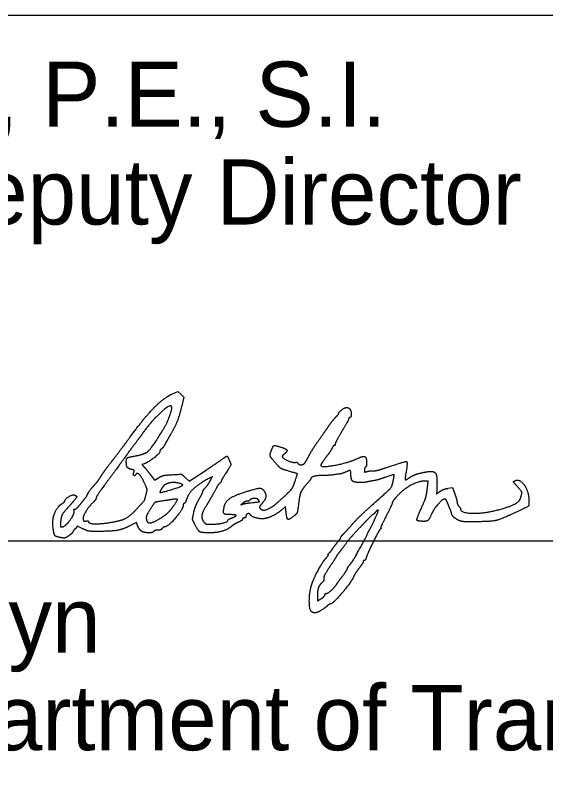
# Model space of a CAD drawing. Extents: x 36.7 to 70.7, y 0 to 22.
# Drawn here: x 62.37 to 63.51, y 7.302 to 8.923 of the extents above; entities that cross this region are included whole.
import ezdxf

# ---------------------------------------------------------------- set-up
doc = ezdxf.new("R2010")
doc.units = 0
for name, color, linetype in [('Default', 7, 'Continuous'), ('SH_Data', 7, 'Continuous'), ('SH_Text', 7, 'Continuous')]:
    doc.layers.add(name, color=color, linetype=linetype)

msp = doc.modelspace()

# ---------------------------------------------------------------- linework, layer by layer
at = {"layer": 'Default'}
for points in [[(62.7066, 8.1089), (62.7192, 8.1148), (62.7255, 8.1084), (62.7319, 8.102), (62.7275, 8.0834)], [(62.6466, 7.959), (62.6416, 7.9574), (62.6468, 7.9522)], [(62.6605, 7.9356), (62.669, 7.924), (62.6778, 7.9293)], [(62.7356, 7.9293), (62.7437, 7.9216), (62.78, 7.9457)], [(62.7895, 7.924), (62.7939, 7.9319), (62.7884, 7.929)], [(63.2553, 7.9081), (63.2568, 7.9219), (63.249, 7.9219)], [(63.2992, 7.9065), (63.3088, 7.908), (63.3139, 7.8944)], [(62.9512, 7.8603), (62.9506, 7.8671), (62.9447, 7.862)], [(62.6336, 7.8247), (62.6303, 7.8327), (62.6164, 7.8259)], [(62.515, 7.8197), (62.5035, 7.8254), (62.4984, 7.8196)], [(63.019, 7.6742), (63.019, 7.6648), (63.0265, 7.6691)]]:
    msp.add_lwpolyline(points, dxfattribs=at)
for points in [[(62.617, 8.017), (62.6467, 8.0576), (62.6885, 8.1005), (62.7066, 8.1089)], [(62.7051, 8.0831), (62.7015, 8.0868), (62.6629, 8.0511), (62.6475, 8.0298)], [(62.6868, 8.0311), (62.6962, 8.046), (62.7082, 8.08), (62.7051, 8.0831)], [(62.7275, 8.0834), (62.7225, 8.0622), (62.7133, 8.0386), (62.7039, 8.0227)], [(63.0646, 8.067), (63.0646, 8.0698), (63.0778, 8.0801), (63.0815, 8.0802)], [(63.0815, 8.0802), (63.0836, 8.0802), (63.0865, 8.079), (63.0881, 8.0774)], [(63.0881, 8.0774), (63.0916, 8.0739), (63.092, 8.0587), (63.0886, 8.0587)], [(63.058, 8.0589), (63.0616, 8.0625), (63.0646, 8.0662), (63.0646, 8.067)], [(63.0442, 8.0417), (63.0482, 8.0475), (63.0544, 8.0553), (63.058, 8.0589)], [(63.0862, 8.0562), (63.0862, 8.0548), (63.0797, 8.0427), (63.0718, 8.0293)], [(63.0886, 8.0587), (63.0873, 8.0587), (63.0862, 8.0575), (63.0862, 8.0562)], [(62.6475, 8.0298), (62.6439, 8.0248), (62.6345, 8.0121), (62.6266, 8.0016)], [(62.6763, 8.0144), (62.6796, 8.0196), (62.6843, 8.0271), (62.6868, 8.0311)], [(63.0226, 8.0107), (63.0305, 8.0219), (63.0403, 8.0358), (63.0442, 8.0417)], [(63.0718, 8.0293), (63.0639, 8.0159), (63.0574, 8.0035), (63.0574, 8.0018)], [(62.5768, 7.9636), (62.5857, 7.9749), (62.6038, 7.999), (62.617, 8.017)], [(62.6265, 7.9758), (62.6471, 7.9795), (62.6611, 7.9904), (62.6763, 8.0144)], [(62.7039, 8.0227), (62.7004, 8.0167), (62.6952, 8.0076), (62.6923, 8.0023)], [(62.6266, 8.0016), (62.6187, 7.9912), (62.6106, 7.9802), (62.6086, 7.9772)], [(62.6923, 8.0023), (62.6895, 7.997), (62.6857, 7.9918), (62.6839, 7.9908)], [(62.9205, 7.9889), (62.9243, 7.998), (62.9274, 7.999), (62.9401, 7.9952)], [(62.9401, 7.9952), (62.9521, 7.9917), (62.955, 7.9855), (62.9473, 7.9797)], [(63.0012, 7.9771), (63.005, 7.9843), (63.0146, 7.9995), (63.0226, 8.0107)], [(63.0554, 7.9987), (63.0543, 7.9987), (63.0519, 7.9957), (63.0501, 7.9921)], [(63.0574, 8.0018), (63.0574, 8.0001), (63.0565, 7.9987), (63.0554, 7.9987)], [(62.6806, 7.9853), (62.6806, 7.9816), (62.6548, 7.9616), (62.6466, 7.959)], [(62.6839, 7.9908), (62.6821, 7.9897), (62.6806, 7.9873), (62.6806, 7.9853)], [(62.9303, 7.9595), (62.9188, 7.9726), (62.9166, 7.9793), (62.9205, 7.9889)], [(62.9473, 7.9797), (62.9446, 7.9776), (62.9431, 7.9748), (62.9441, 7.9734)], [(63.0501, 7.9921), (63.0483, 7.9884), (63.0422, 7.9794), (63.0365, 7.9719)], [(62.5553, 7.9342), (62.5583, 7.939), (62.568, 7.9523), (62.5768, 7.9636)], [(62.6086, 7.9772), (62.6066, 7.9742), (62.5913, 7.9533), (62.5745, 7.9306)], [(62.6086, 7.9636), (62.6086, 7.9705), (62.6127, 7.9733), (62.6265, 7.9758)], [(62.6196, 7.9472), (62.6124, 7.949), (62.6086, 7.9547), (62.6086, 7.9636)], [(62.78, 7.9457), (62.7999, 7.959), (62.8175, 7.9709), (62.8191, 7.9723)], [(62.8191, 7.9723), (62.8236, 7.976), (62.826, 7.9752), (62.829, 7.9686)], [(62.829, 7.9686), (62.8334, 7.9589), (62.8324, 7.9548), (62.8222, 7.939)], [(62.9441, 7.9734), (62.9467, 7.9696), (62.9666, 7.9614), (62.9713, 7.9622)], [(62.9713, 7.9622), (62.9735, 7.9626), (62.9761, 7.9618), (62.9769, 7.9604)], [(62.9919, 7.9609), (62.9932, 7.9625), (62.9974, 7.9698), (63.0012, 7.9771)], [(63.0365, 7.9719), (63.0308, 7.9644), (63.0262, 7.9572), (63.0262, 7.9558)], [(63.0262, 7.9558), (63.0262, 7.9505), (63.0858, 7.9615), (63.1038, 7.97)], [(63.1038, 7.97), (63.1167, 7.9762), (63.1246, 7.9731), (63.1246, 7.9617)], [(63.1669, 7.951), (63.2073, 7.9648), (63.2132, 7.9632), (63.2091, 7.9393)], [(62.6247, 7.941), (62.6256, 7.9445), (62.6244, 7.946), (62.6196, 7.9472)], [(62.6468, 7.9522), (62.6496, 7.9494), (62.6558, 7.9419), (62.6605, 7.9356)], [(62.9538, 7.9444), (62.943, 7.9475), (62.9381, 7.9506), (62.9303, 7.9595)], [(62.9769, 7.9604), (62.9791, 7.9569), (62.9891, 7.9572), (62.9919, 7.9609)], [(63.1222, 7.9519), (63.1209, 7.9511), (63.1198, 7.9482), (63.1198, 7.9456)], [(63.1246, 7.9617), (63.1246, 7.9571), (63.1235, 7.9527), (63.1222, 7.9519)], [(63.1381, 7.9439), (63.1423, 7.9438), (63.1552, 7.9469), (63.1669, 7.951)], [(62.539, 7.9123), (62.5456, 7.9197), (62.5498, 7.9254), (62.5553, 7.9342)], [(62.5745, 7.9306), (62.5577, 7.908), (62.5439, 7.8879), (62.5438, 7.8859)], [(62.629, 7.9362), (62.6265, 7.9323), (62.6233, 7.9359), (62.6247, 7.941)], [(62.6477, 7.9176), (62.6416, 7.9313), (62.6319, 7.9409), (62.629, 7.9362)], [(62.6778, 7.9293), (62.6843, 7.9331), (62.6919, 7.9348), (62.707, 7.9357)], [(62.707, 7.9357), (62.7273, 7.9369), (62.7275, 7.9368), (62.7356, 7.9293)], [(62.8222, 7.939), (62.8169, 7.9308), (62.8126, 7.9232), (62.8126, 7.9221)], [(62.9706, 7.9206), (62.9763, 7.9374), (62.9759, 7.938), (62.9538, 7.9444)], [(63.0288, 7.9339), (63.0173, 7.9339), (63.0046, 7.9301), (63.0046, 7.9267)], [(63.0796, 7.9412), (63.074, 7.9383), (63.0438, 7.9339), (63.0288, 7.9339)], [(63.091, 7.9365), (63.091, 7.9439), (63.0873, 7.9454), (63.0796, 7.9412)], [(63.1103, 7.9189), (63.0979, 7.9189), (63.091, 7.9252), (63.091, 7.9365)], [(63.1198, 7.9456), (63.1198, 7.9417), (63.1208, 7.9411), (63.1252, 7.9425)], [(63.1252, 7.9425), (63.1282, 7.9434), (63.134, 7.9441), (63.1381, 7.9439)], [(63.1822, 7.9243), (63.1843, 7.9358), (63.1826, 7.9362), (63.1616, 7.929)], [(63.2091, 7.9393), (63.2078, 7.9317), (63.207, 7.9251), (63.2075, 7.9246)], [(63.2151, 7.9285), (63.2223, 7.9335), (63.2405, 7.9398), (63.2542, 7.942)], [(63.2542, 7.942), (63.2688, 7.9443), (63.2765, 7.9339), (63.2757, 7.9126)], [(62.651, 7.8931), (62.6536, 7.9029), (62.6533, 7.9051), (62.6477, 7.9176)], [(62.7188, 7.918), (62.7079, 7.9201), (62.6905, 7.915), (62.6862, 7.9085)], [(62.7082, 7.9044), (62.7274, 7.9103), (62.7314, 7.9154), (62.7188, 7.918)], [(62.7884, 7.929), (62.765, 7.9165), (62.7423, 7.8958), (62.7381, 7.8833)], [(62.7767, 7.9059), (62.7821, 7.9118), (62.7846, 7.9154), (62.7895, 7.924)], [(62.809, 7.9171), (62.8071, 7.9155), (62.804, 7.9113), (62.8021, 7.9078)], [(62.8126, 7.9221), (62.8126, 7.921), (62.811, 7.9187), (62.809, 7.9171)], [(62.9523, 7.8933), (62.9627, 7.9033), (62.9668, 7.9095), (62.9706, 7.9206)], [(62.9952, 7.9147), (62.9868, 7.9052), (62.981, 7.8926), (62.9794, 7.8799)], [(63.0046, 7.9267), (63.0046, 7.9258), (63.0004, 7.9204), (62.9952, 7.9147)], [(63.127, 7.9203), (63.1237, 7.9195), (63.1162, 7.9189), (63.1103, 7.9189)], [(63.1402, 7.9229), (63.1362, 7.9223), (63.1303, 7.9211), (63.127, 7.9203)], [(63.1374, 7.8714), (63.1729, 7.9029), (63.1798, 7.9111), (63.1822, 7.9243)], [(63.1616, 7.929), (63.1538, 7.9263), (63.1442, 7.9235), (63.1402, 7.9229)], [(63.249, 7.9219), (63.2363, 7.9219), (63.2025, 7.9035), (63.1904, 7.8899)], [(63.2075, 7.9246), (63.2079, 7.9241), (63.2113, 7.9259), (63.2151, 7.9285)], [(63.4458, 7.9133), (63.4405, 7.9189), (63.4402, 7.9216), (63.4449, 7.9234)], [(63.4449, 7.9234), (63.4535, 7.9267), (63.4719, 7.9017), (63.4729, 7.8855)], [(62.5246, 7.8919), (62.5246, 7.8935), (62.5337, 7.9065), (62.539, 7.9123)], [(62.6862, 7.9085), (62.6792, 7.8977), (62.6837, 7.8969), (62.7082, 7.9044)], [(62.7642, 7.8818), (62.7686, 7.8894), (62.7725, 7.8971), (62.7727, 7.8988)], [(62.7727, 7.8988), (62.773, 7.9006), (62.7748, 7.9037), (62.7767, 7.9059)], [(62.8021, 7.9078), (62.794, 7.8924), (62.7862, 7.8787), (62.7801, 7.8689)], [(62.856, 7.8961), (62.8878, 7.9067), (62.9012, 7.9071), (62.9063, 7.8977)], [(62.9063, 7.8977), (62.9095, 7.8916), (62.9061, 7.8803), (62.8987, 7.8724)], [(63.2407, 7.8602), (63.2497, 7.8801), (63.2537, 7.8933), (63.2553, 7.9081)], [(63.2757, 7.9126), (63.275, 7.8942), (63.2749, 7.8945), (63.2826, 7.9)], [(63.2826, 7.9), (63.2864, 7.9027), (63.2939, 7.9056), (63.2992, 7.9065)], [(63.4549, 7.8842), (63.4589, 7.896), (63.4573, 7.9009), (63.4458, 7.9133)], [(62.4766, 7.8798), (62.4767, 7.8836), (62.4934, 7.8936), (62.4972, 7.8921)], [(62.4972, 7.8921), (62.5032, 7.8898), (62.5009, 7.885), (62.4866, 7.869)], [(62.5101, 7.8727), (62.5154, 7.8793), (62.5209, 7.886), (62.5222, 7.8876)], [(62.5222, 7.8876), (62.5235, 7.8892), (62.5246, 7.8911), (62.5246, 7.8919)], [(62.5438, 7.8859), (62.5437, 7.8839), (62.5404, 7.8791), (62.5364, 7.8751)], [(62.6314, 7.8626), (62.6475, 7.8802), (62.6478, 7.8807), (62.651, 7.8931)], [(62.7064, 7.8823), (62.7008, 7.8814), (62.693, 7.8802), (62.689, 7.8796)], [(62.7114, 7.8706), (62.7192, 7.882), (62.7183, 7.8842), (62.7064, 7.8823)], [(62.7381, 7.8833), (62.7364, 7.8781), (62.7341, 7.8739), (62.733, 7.8739)], [(62.7533, 7.8539), (62.7549, 7.8616), (62.7598, 7.8741), (62.7642, 7.8818)], [(62.8184, 7.8651), (62.8205, 7.8763), (62.8367, 7.8897), (62.856, 7.8961)], [(62.8921, 7.8819), (62.8893, 7.8853), (62.8759, 7.8845), (62.8736, 7.8808)], [(62.8762, 7.8755), (62.8929, 7.8771), (62.8953, 7.878), (62.8921, 7.8819)], [(62.8953, 7.8645), (62.9006, 7.8558), (62.9273, 7.8693), (62.9523, 7.8933)], [(63.1904, 7.8899), (63.1845, 7.8834), (63.1798, 7.8769), (63.1798, 7.8753)], [(63.2922, 7.8835), (63.2879, 7.8835), (63.2696, 7.863), (63.2649, 7.8528)], [(63.2978, 7.8769), (63.2963, 7.8805), (63.2938, 7.8835), (63.2922, 7.8835)], [(63.3139, 7.8944), (63.3167, 7.887), (63.319, 7.8789), (63.319, 7.8764)], [(63.406, 7.8599), (63.4297, 7.8661), (63.4527, 7.8775), (63.4549, 7.8842)], [(63.4729, 7.8855), (63.4738, 7.8701), (63.4712, 7.867), (63.4478, 7.856)], [(62.4517, 7.8182), (62.4488, 7.8368), (62.4595, 7.8668), (62.4719, 7.8745)], [(62.4866, 7.869), (62.4729, 7.8539), (62.4679, 7.8437), (62.4673, 7.8299)], [(62.4719, 7.8745), (62.4745, 7.8761), (62.4766, 7.8785), (62.4766, 7.8798)], [(62.4978, 7.8614), (62.4992, 7.861), (62.5047, 7.8661), (62.5101, 7.8727)], [(62.5364, 7.8751), (62.5266, 7.8655), (62.5142, 7.8434), (62.516, 7.8387)], [(62.689, 7.8796), (62.6712, 7.877), (62.6692, 7.8759), (62.6619, 7.8647)], [(62.6815, 7.842), (62.6927, 7.8489), (62.7037, 7.8595), (62.7114, 7.8706)], [(62.7309, 7.8709), (62.7308, 7.8623), (62.6977, 7.8235), (62.6906, 7.8235)], [(62.733, 7.8739), (62.7319, 7.8739), (62.731, 7.8725), (62.7309, 7.8709)], [(62.7801, 7.8689), (62.7721, 7.8563), (62.7699, 7.8411), (62.775, 7.8343)], [(62.8319, 7.8499), (62.8204, 7.8499), (62.8164, 7.8544), (62.8184, 7.8651)], [(62.8592, 7.8749), (62.8547, 7.8711), (62.8547, 7.8711), (62.8594, 7.8728)], [(62.8681, 7.8787), (62.8658, 7.8787), (62.8618, 7.877), (62.8592, 7.8749)], [(62.8594, 7.8728), (62.862, 7.8737), (62.8696, 7.8749), (62.8762, 7.8755)], [(62.8736, 7.8808), (62.8729, 7.8796), (62.8704, 7.8787), (62.8681, 7.8787)], [(62.8987, 7.8724), (62.8959, 7.8694), (62.8944, 7.8659), (62.8953, 7.8645)], [(62.9794, 7.8799), (62.9766, 7.8574), (62.9749, 7.8519), (62.9692, 7.8474)], [(63.0933, 7.8286), (63.1005, 7.837), (63.1203, 7.8562), (63.1374, 7.8714)], [(63.1798, 7.8753), (63.1798, 7.8737), (63.1738, 7.8609), (63.1666, 7.8468)], [(63.3037, 7.8627), (63.3019, 7.8669), (63.2993, 7.8732), (63.2978, 7.8769)], [(63.319, 7.8764), (63.319, 7.8739), (63.3206, 7.8702), (63.3226, 7.8682)], [(63.3226, 7.8682), (63.3246, 7.8662), (63.3262, 7.8635), (63.3262, 7.8622)], [(62.4721, 7.8239), (62.4785, 7.8249), (62.4986, 7.8533), (62.4966, 7.8585)], [(62.4966, 7.8585), (62.4958, 7.8605), (62.4964, 7.8618), (62.4978, 7.8614)], [(62.5749, 7.8332), (62.5976, 7.8369), (62.6172, 7.8471), (62.6314, 7.8626)], [(62.6619, 7.8647), (62.6537, 7.8521), (62.6505, 7.8422), (62.6528, 7.8364)], [(62.7553, 7.8299), (62.7509, 7.839), (62.7507, 7.8412), (62.7533, 7.8539)], [(62.8353, 7.843), (62.8456, 7.8467), (62.844, 7.8499), (62.8319, 7.8499)], [(62.8749, 7.85), (62.8729, 7.8533), (62.8654, 7.8502), (62.8654, 7.846)], [(62.9062, 7.8415), (62.8976, 7.84), (62.8778, 7.8453), (62.8749, 7.85)], [(62.9447, 7.862), (62.9353, 7.8538), (62.9153, 7.8432), (62.9062, 7.8415)], [(62.9692, 7.8474), (62.9575, 7.8382), (62.9531, 7.8413), (62.9512, 7.8603)], [(63.0907, 7.7448), (63.0983, 7.7535), (63.1516, 7.8573), (63.1495, 7.8594)], [(63.138, 7.8499), (63.1373, 7.8499), (63.1333, 7.8464), (63.1292, 7.8421)], [(63.1438, 7.8553), (63.1414, 7.8523), (63.1388, 7.8499), (63.138, 7.8499)], [(63.1495, 7.8594), (63.1488, 7.8601), (63.1462, 7.8582), (63.1438, 7.8553)], [(63.248, 7.8355), (63.2335, 7.8355), (63.2319, 7.8409), (63.2407, 7.8602)], [(63.2649, 7.8528), (63.2592, 7.8404), (63.2544, 7.8355), (63.248, 7.8355)], [(63.3071, 7.8531), (63.307, 7.8542), (63.3055, 7.8586), (63.3037, 7.8627)], [(63.3227, 7.8375), (63.3157, 7.8409), (63.3072, 7.8493), (63.3071, 7.8531)], [(63.3262, 7.8622), (63.3262, 7.8537), (63.3768, 7.8522), (63.406, 7.8599)], [(63.4478, 7.856), (63.413, 7.8397), (63.392, 7.8349), (63.3526, 7.8345)], [(62.516, 7.8387), (62.5169, 7.8363), (62.5192, 7.8354), (62.5222, 7.8362)], [(62.5222, 7.8362), (62.5248, 7.8369), (62.527, 7.8365), (62.527, 7.8354)], [(62.527, 7.8354), (62.527, 7.8308), (62.5526, 7.8296), (62.5749, 7.8332)], [(62.6528, 7.8364), (62.6548, 7.8312), (62.6683, 7.8338), (62.6815, 7.842)], [(62.775, 7.8343), (62.7779, 7.8305), (62.7814, 7.8295), (62.7926, 7.8295)], [(62.7926, 7.8295), (62.8066, 7.8295), (62.827, 7.8346), (62.827, 7.8381)], [(62.827, 7.8381), (62.827, 7.8391), (62.8307, 7.8413), (62.8353, 7.843)], [(62.8528, 7.8353), (62.8455, 7.832), (62.8378, 7.8275), (62.8336, 7.824)], [(62.8582, 7.8402), (62.8582, 7.8389), (62.8558, 7.8367), (62.8528, 7.8353)], [(62.8618, 7.8427), (62.8598, 7.8427), (62.8582, 7.8416), (62.8582, 7.8402)], [(62.8654, 7.846), (62.8654, 7.8442), (62.8638, 7.8427), (62.8618, 7.8427)], [(63.1292, 7.8421), (63.1251, 7.8378), (63.1146, 7.8267), (63.1058, 7.8174)], [(63.1666, 7.8468), (63.1593, 7.8326), (63.1542, 7.8211), (63.1552, 7.821)], [(63.3526, 7.8345), (63.3377, 7.8343), (63.3274, 7.8354), (63.3227, 7.8375)], [(62.4683, 7.8005), (62.4574, 7.8025), (62.4536, 7.8066), (62.4517, 7.8182)], [(62.4673, 7.8299), (62.4671, 7.8243), (62.4679, 7.8233), (62.4721, 7.8239)], [(62.4984, 7.8196), (62.4957, 7.8164), (62.4934, 7.813), (62.4934, 7.8121)], [(62.5458, 7.8139), (62.5302, 7.8139), (62.5243, 7.815), (62.515, 7.8197)], [(62.6164, 7.8259), (62.6009, 7.8181), (62.5757, 7.8139), (62.5458, 7.8139)], [(62.6418, 7.8141), (62.6392, 7.8155), (62.6355, 7.8203), (62.6336, 7.8247)], [(62.6854, 7.8199), (62.6837, 7.8179), (62.6794, 7.8163), (62.6756, 7.8163)], [(62.6906, 7.8235), (62.6894, 7.8235), (62.687, 7.8219), (62.6854, 7.8199)], [(62.7871, 7.8108), (62.7696, 7.8109), (62.7626, 7.8151), (62.7553, 7.8299)], [(62.8336, 7.824), (62.8259, 7.8176), (62.8016, 7.8107), (62.7871, 7.8108)], [(63.0748, 7.8082), (63.0778, 7.811), (63.0861, 7.8202), (63.0933, 7.8286)], [(63.1058, 7.8174), (63.097, 7.8082), (63.0871, 7.7969), (63.0838, 7.7925)], [(63.1544, 7.8192), (63.1517, 7.8174), (63.1265, 7.7664), (63.1235, 7.7569)], [(63.1552, 7.821), (63.1562, 7.821), (63.1558, 7.8202), (63.1544, 7.8192)], [(62.485, 7.8046), (62.4785, 7.8001), (62.4749, 7.7993), (62.4683, 7.8005)], [(62.4934, 7.8121), (62.4934, 7.8111), (62.4896, 7.8077), (62.485, 7.8046)], [(62.6674, 7.8139), (62.6654, 7.8107), (62.6479, 7.8108), (62.6418, 7.8141)], [(62.6756, 7.8163), (62.6719, 7.8163), (62.6682, 7.8152), (62.6674, 7.8139)], [(63.0628, 7.7912), (63.0664, 7.7954), (63.0694, 7.7998), (63.0694, 7.801)], [(63.0694, 7.801), (63.0695, 7.8021), (63.0719, 7.8054), (63.0748, 7.8082)], [(63.0526, 7.7779), (63.0546, 7.7809), (63.0592, 7.7869), (63.0628, 7.7912)], [(63.0838, 7.7925), (63.0757, 7.7815), (63.0652, 7.7677), (63.0622, 7.7642)], [(63.0422, 7.7635), (63.0413, 7.7635), (63.0425, 7.7655), (63.0448, 7.7679)], [(63.0448, 7.7679), (63.0471, 7.7703), (63.0506, 7.7748), (63.0526, 7.7779)], [(63.0088, 7.7055), (63.0147, 7.7203), (63.0318, 7.7502), (63.0389, 7.7581)], [(63.0389, 7.7581), (63.0416, 7.761), (63.0431, 7.7635), (63.0422, 7.7635)], [(63.0598, 7.7603), (63.0598, 7.7597), (63.0535, 7.7498), (63.0457, 7.7382)], [(63.0622, 7.7642), (63.0609, 7.7626), (63.0598, 7.7608), (63.0598, 7.7603)], [(63.1196, 7.7515), (63.1184, 7.7515), (63.1174, 7.7503), (63.1174, 7.749)], [(63.1235, 7.7569), (63.1226, 7.7539), (63.1209, 7.7515), (63.1196, 7.7515)], [(63.0457, 7.7382), (63.037, 7.7251), (63.0321, 7.7154), (63.0328, 7.7127)], [(63.0838, 7.7345), (63.0838, 7.7358), (63.0869, 7.7405), (63.0907, 7.7448)], [(63.1174, 7.749), (63.1174, 7.7476), (63.1131, 7.7408), (63.1079, 7.7339)], [(63.0736, 7.7187), (63.0792, 7.726), (63.0838, 7.7332), (63.0838, 7.7345)], [(63.1079, 7.7339), (63.1027, 7.727), (63.0976, 7.719), (63.0965, 7.7162)], [(63.007, 7.641), (63.0011, 7.6448), (63.0023, 7.6891), (63.0088, 7.7055)], [(63.0291, 7.7041), (63.0232, 7.6989), (63.019, 7.6865), (63.019, 7.6742)], [(63.0328, 7.7127), (63.0335, 7.7101), (63.0319, 7.7065), (63.0291, 7.7041)], [(63.0965, 7.7162), (63.0929, 7.7064), (63.0517, 7.6579), (63.047, 7.6579)], [(63.061, 7.7014), (63.0623, 7.7035), (63.068, 7.7113), (63.0736, 7.7187)], [(63.0382, 7.6807), (63.0401, 7.6795), (63.0568, 7.6946), (63.061, 7.7014)], [(63.0265, 7.6691), (63.0307, 7.6715), (63.0346, 7.6754), (63.0352, 7.6776)], [(63.0352, 7.6776), (63.0358, 7.6799), (63.0372, 7.6813), (63.0382, 7.6807)], [(63.047, 7.6579), (63.0456, 7.6579), (63.0423, 7.6558), (63.0395, 7.6533)], [(63.0135, 7.6387), (63.0119, 7.6387), (63.009, 7.6398), (63.007, 7.641)], [(63.0395, 7.6533), (63.0333, 7.6476), (63.0174, 7.6387), (63.0135, 7.6387)]]:
    msp.add_open_spline(points, degree=2, dxfattribs=at)
at = {"layer": 'SH_Data'}
for p, q in [((61.2213, 8.9231), (64.7213, 8.9231)), ((61.2213, 7.7937), (64.7213, 7.7937))]:
    msp.add_line(p, q, dxfattribs=at)

# ---------------------------------------------------------------- texts
at = {"layer": 'SH_Text'}
for s, p in [('Pat McColley, P.E., S.I.', (61.2213, 8.6832)), ('District       Deputy Director', (61.2213, 8.4732)), ('Pamela Boratyn', (61.2213, 7.5537)), ('Director, Department of Transportation', (61.2213, 7.3437))]:
    msp.add_text(s, height=0.14, dxfattribs=at).set_placement(p)

doc.saveas('drawing.dxf')
